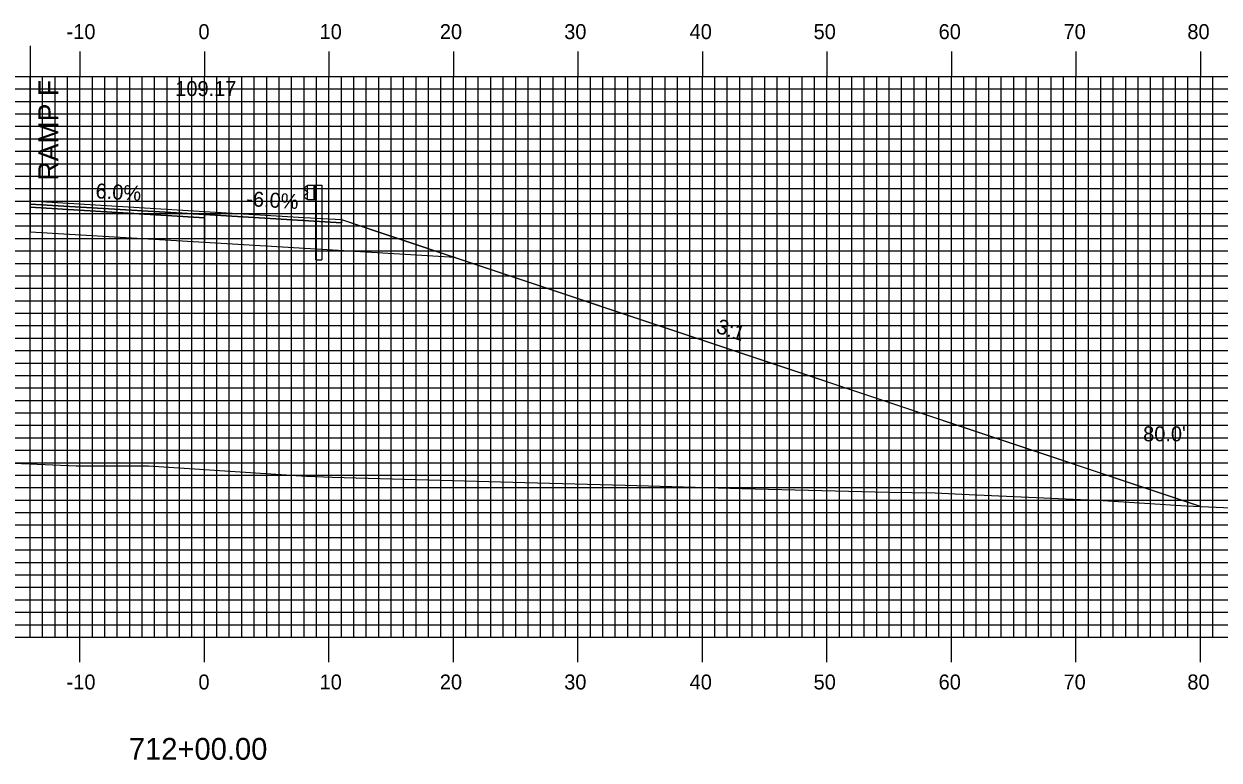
# Model space of a CAD drawing. Extents: x 855297 to 855640, y 364366 to 364586.
# Drawn here: x 855448.3 to 855544.3, y 364433.9 to 364493 of the extents above; entities that cross this region are included whole.
import ezdxf

# ---------------------------------------------------------------- set-up
doc = ezdxf.new("R2010")
doc.units = 0
for name, color, linetype in [('ANNOTATION', 7, 'Continuous'), ('D_Drainage_Culvert', 7, 'Continuous'), ('D_Guardrail_Beam_Rt', 7, 'Continuous'), ('D_Roadway_Centerline', 7, 'Continuous'), ('D_Roadway_Centerline_Text', 7, 'Continuous'), ('D_Roadway_Edge_Shoulder', 7, 'Continuous'), ('D_Roadway_Edge_TW', 7, 'Continuous'), ('D_Roadway_Pavement', 7, 'Continuous'), ('D_Roadway_SlopeLines', 7, 'Continuous'), ('D_Roadway_SubGrade', 7, 'Continuous'), ('D_Text_Standard', 7, 'Continuous'), ('H_V ANNOTATION', 7, 'Continuous'), ('MAJOR', 7, 'Continuous'), ('MINOR', 7, 'Continuous'), ('S_Roadway_Centerline', 7, 'Continuous')]:
    doc.layers.add(name, color=color, linetype=linetype)

msp = doc.modelspace()

# ---------------------------------------------------------------- linework, layer by layer
at = {"layer": 'D_Drainage_Culvert'}
msp.add_lwpolyline([(855473.77, 364477.294), (855476.77, 364476.294), (855542.672, 364454.326)], dxfattribs=at)
at = {"layer": 'D_Guardrail_Beam_Rt'}
for p, q in [((855470.951, 364479.953), (855470.807, 364479.853)), ((855470.807, 364479.71), (855471.003, 364479.573)), ((855471.003, 364479.374), (855470.807, 364479.238)), ((855471.041, 364479.974), (855470.967, 364479.959)), ((855471.036, 364479.509), (855471.036, 364479.439)), ((855471.041, 364480.057), (855471.728, 364480.057)), ((855471.041, 364478.891), (855471.041, 364480.057)), ((855471.562, 364480.057), (855471.562, 364478.891)), ((855471.666, 364480.057), (855471.666, 364478.891)), ((855471.728, 364480.057), (855472.199, 364480.057)), ((855471.728, 364480.057), (855471.728, 364478.891)), ((855472.199, 364480.057), (855472.199, 364474.057)), ((855470.807, 364479.095), (855470.951, 364478.995)), ((855470.967, 364478.989), (855471.041, 364478.974)), ((855471.728, 364478.891), (855471.041, 364478.891)), ((855471.707, 364474.057), (855471.707, 364478.891)), ((855471.707, 364474.057), (855472.199, 364474.057))]:
    msp.add_line(p, q, dxfattribs=at)
for centre, major_axis, start_param, end_param in [((855470.858, 364479.781), (-0.0877, 0), 5.323254, 7.243116), ((855470.975, 364479.919), (-0.0417, 0), 4.907132, 5.323254), ((855470.957, 364479.509), (0.0789, 0), 0, 0.959931), ((855470.957, 364479.439), (0.0789, 0), 5.323254, 6.283185), ((855470.858, 364479.167), (-0.0877, 0), 5.323254, 7.243116), ((855470.975, 364479.029), (-0.0417, 0), 0.959931, 1.376053)]:
    msp.add_ellipse(centre, major_axis=major_axis, ratio=0.995501, start_param=start_param, end_param=end_param, dxfattribs=at)
at = {"layer": 'D_Roadway_Centerline'}
msp.add_lwpolyline([(855448.77, 364478.794), (855462.77, 364477.954), (855470.77, 364477.474), (855473.77, 364477.294), (855482.916, 364474.245), (855542.672, 364454.326)], dxfattribs=at)
at = {"layer": 'D_Roadway_Edge_Shoulder'}
msp.add_lwpolyline([(855462.77, 364477.954), (855470.77, 364477.474), (855470.77, 364477.474), (855473.77, 364477.294), (855473.77, 364477.044), (855462.77, 364477.704)], close=True, dxfattribs=at)
at = {"layer": 'D_Roadway_Edge_TW'}
msp.add_lwpolyline([(855448.77, 364478.794), (855462.77, 364477.954), (855462.77, 364477.704), (855448.77, 364478.544)], close=True, dxfattribs=at)
at = {"layer": 'D_Roadway_Pavement'}
msp.add_lwpolyline([(855448.77, 364478.544), (855462.77, 364477.704), (855462.77, 364477.454), (855448.77, 364478.294)], close=True, dxfattribs=at)
msp.add_lwpolyline([(855462.77, 364477.704), (855462.77, 364477.454)], dxfattribs=at)
msp.add_lwpolyline([(855462.77, 364477.704), (855462.77, 364477.454)], dxfattribs=at)
at = {"layer": 'D_Roadway_SlopeLines'}
msp.add_line((855473.77, 364477.294), (855542.801, 364454.284), dxfattribs=at)
at = {"layer": 'D_Roadway_SubGrade'}
msp.add_line((855448.77, 364491.251), (855448.77, 364476.294), dxfattribs=at)
for points in [[(855448.77, 364478.294), (855462.77, 364477.454), (855462.77, 364475.454), (855448.77, 364476.294)], [(855462.77, 364477.454), (855462.77, 364477.704), (855473.77, 364477.044), (855473.77, 364477.294), (855482.916, 364474.245), (855462.77, 364475.454)]]:
    msp.add_lwpolyline(points, close=True, dxfattribs=at)
at = {"layer": 'MAJOR'}
for p, q in [((855452.77, 364490.791), (855452.77, 364488.787)), ((855462.77, 364490.791), (855462.77, 364488.787)), ((855472.77, 364490.791), (855472.77, 364488.787)), ((855482.77, 364490.791), (855482.77, 364488.787)), ((855492.77, 364490.791), (855492.77, 364488.787)), ((855502.77, 364490.791), (855502.77, 364488.787)), ((855512.77, 364490.791), (855512.77, 364488.787)), ((855522.77, 364490.791), (855522.77, 364488.787)), ((855532.77, 364490.791), (855532.77, 364488.787)), ((855542.77, 364490.791), (855542.77, 364488.787)), ((855322.77, 364488.787), (855602.77, 364488.787)), ((855322.77, 364488.787), (855602.77, 364488.787)), ((855452.77, 364443.787), (855452.77, 364488.787)), ((855462.77, 364443.787), (855462.77, 364488.787)), ((855472.77, 364443.787), (855472.77, 364488.787)), ((855482.77, 364443.787), (855482.77, 364488.787)), ((855492.77, 364443.787), (855492.77, 364488.787)), ((855502.77, 364443.787), (855502.77, 364488.787)), ((855512.77, 364443.787), (855512.77, 364488.787)), ((855522.77, 364443.787), (855522.77, 364488.787)), ((855532.77, 364443.787), (855532.77, 364488.787)), ((855542.77, 364443.787), (855542.77, 364488.787)), ((855322.77, 364483.787), (855602.77, 364483.787)), ((855322.77, 364478.787), (855602.77, 364478.787)), ((855322.77, 364473.787), (855602.77, 364473.787)), ((855322.77, 364468.787), (855602.77, 364468.787)), ((855322.77, 364463.787), (855602.77, 364463.787)), ((855322.77, 364458.787), (855602.77, 364458.787)), ((855322.77, 364453.787), (855602.77, 364453.787)), ((855322.77, 364448.787), (855602.77, 364448.787)), ((855322.77, 364443.787), (855602.77, 364443.787)), ((855322.77, 364443.787), (855602.77, 364443.787)), ((855452.77, 364441.783), (855452.77, 364443.787)), ((855462.77, 364441.783), (855462.77, 364443.787)), ((855472.77, 364441.783), (855472.77, 364443.787)), ((855482.77, 364441.783), (855482.77, 364443.787)), ((855492.77, 364441.783), (855492.77, 364443.787)), ((855502.77, 364441.783), (855502.77, 364443.787)), ((855512.77, 364441.783), (855512.77, 364443.787)), ((855522.77, 364441.783), (855522.77, 364443.787)), ((855532.77, 364441.783), (855532.77, 364443.787)), ((855542.77, 364441.783), (855542.77, 364443.787))]:
    msp.add_line(p, q, dxfattribs=at)
at = {"layer": 'MINOR'}
for p, q in [((855448.77, 364443.787), (855448.77, 364488.787)), ((855449.77, 364443.787), (855449.77, 364488.787)), ((855450.77, 364443.787), (855450.77, 364488.787)), ((855451.77, 364443.787), (855451.77, 364488.787)), ((855453.77, 364443.787), (855453.77, 364488.787)), ((855454.77, 364443.787), (855454.77, 364488.787)), ((855455.77, 364443.787), (855455.77, 364488.787)), ((855456.77, 364443.787), (855456.77, 364488.787)), ((855457.77, 364443.787), (855457.77, 364488.787)), ((855458.77, 364443.787), (855458.77, 364488.787)), ((855459.77, 364443.787), (855459.77, 364488.787)), ((855460.77, 364443.787), (855460.77, 364488.787)), ((855461.77, 364443.787), (855461.77, 364488.787)), ((855463.77, 364443.787), (855463.77, 364488.787)), ((855464.77, 364443.787), (855464.77, 364488.787)), ((855465.77, 364443.787), (855465.77, 364488.787)), ((855466.77, 364443.787), (855466.77, 364488.787)), ((855467.77, 364443.787), (855467.77, 364488.787)), ((855468.77, 364443.787), (855468.77, 364488.787)), ((855469.77, 364443.787), (855469.77, 364488.787)), ((855470.77, 364443.787), (855470.77, 364488.787)), ((855471.77, 364443.787), (855471.77, 364488.787)), ((855473.77, 364443.787), (855473.77, 364488.787)), ((855474.77, 364443.787), (855474.77, 364488.787)), ((855475.77, 364443.787), (855475.77, 364488.787)), ((855476.77, 364443.787), (855476.77, 364488.787)), ((855477.77, 364443.787), (855477.77, 364488.787)), ((855478.77, 364443.787), (855478.77, 364488.787)), ((855479.77, 364443.787), (855479.77, 364488.787)), ((855480.77, 364443.787), (855480.77, 364488.787)), ((855481.77, 364443.787), (855481.77, 364488.787)), ((855483.77, 364443.787), (855483.77, 364488.787)), ((855484.77, 364443.787), (855484.77, 364488.787)), ((855485.77, 364443.787), (855485.77, 364488.787)), ((855486.77, 364443.787), (855486.77, 364488.787)), ((855487.77, 364443.787), (855487.77, 364488.787)), ((855488.77, 364443.787), (855488.77, 364488.787)), ((855489.77, 364443.787), (855489.77, 364488.787)), ((855490.77, 364443.787), (855490.77, 364488.787)), ((855491.77, 364443.787), (855491.77, 364488.787)), ((855493.77, 364443.787), (855493.77, 364488.787)), ((855494.77, 364443.787), (855494.77, 364488.787)), ((855495.77, 364443.787), (855495.77, 364488.787)), ((855496.77, 364443.787), (855496.77, 364488.787)), ((855497.77, 364443.787), (855497.77, 364488.787)), ((855498.77, 364443.787), (855498.77, 364488.787)), ((855499.77, 364443.787), (855499.77, 364488.787)), ((855500.77, 364443.787), (855500.77, 364488.787)), ((855501.77, 364443.787), (855501.77, 364488.787)), ((855503.77, 364443.787), (855503.77, 364488.787)), ((855504.77, 364443.787), (855504.77, 364488.787)), ((855505.77, 364443.787), (855505.77, 364488.787)), ((855506.77, 364443.787), (855506.77, 364488.787)), ((855507.77, 364443.787), (855507.77, 364488.787)), ((855508.77, 364443.787), (855508.77, 364488.787)), ((855509.77, 364443.787), (855509.77, 364488.787)), ((855510.77, 364443.787), (855510.77, 364488.787)), ((855511.77, 364443.787), (855511.77, 364488.787)), ((855513.77, 364443.787), (855513.77, 364488.787)), ((855514.77, 364443.787), (855514.77, 364488.787)), ((855515.77, 364443.787), (855515.77, 364488.787)), ((855516.77, 364443.787), (855516.77, 364488.787)), ((855517.77, 364443.787), (855517.77, 364488.787)), ((855518.77, 364443.787), (855518.77, 364488.787)), ((855519.77, 364443.787), (855519.77, 364488.787)), ((855520.77, 364443.787), (855520.77, 364488.787)), ((855521.77, 364443.787), (855521.77, 364488.787)), ((855523.77, 364443.787), (855523.77, 364488.787)), ((855524.77, 364443.787), (855524.77, 364488.787)), ((855525.77, 364443.787), (855525.77, 364488.787)), ((855526.77, 364443.787), (855526.77, 364488.787)), ((855527.77, 364443.787), (855527.77, 364488.787)), ((855528.77, 364443.787), (855528.77, 364488.787)), ((855529.77, 364443.787), (855529.77, 364488.787)), ((855530.77, 364443.787), (855530.77, 364488.787)), ((855531.77, 364443.787), (855531.77, 364488.787)), ((855533.77, 364443.787), (855533.77, 364488.787)), ((855534.77, 364443.787), (855534.77, 364488.787)), ((855535.77, 364443.787), (855535.77, 364488.787)), ((855536.77, 364443.787), (855536.77, 364488.787)), ((855537.77, 364443.787), (855537.77, 364488.787)), ((855538.77, 364443.787), (855538.77, 364488.787)), ((855539.77, 364443.787), (855539.77, 364488.787)), ((855540.77, 364443.787), (855540.77, 364488.787)), ((855541.77, 364443.787), (855541.77, 364488.787)), ((855543.77, 364443.787), (855543.77, 364488.787)), ((855322.77, 364487.787), (855602.77, 364487.787)), ((855322.77, 364486.787), (855602.77, 364486.787)), ((855322.77, 364485.787), (855602.77, 364485.787)), ((855322.77, 364484.787), (855602.77, 364484.787)), ((855322.77, 364482.787), (855602.77, 364482.787)), ((855322.77, 364481.787), (855602.77, 364481.787)), ((855322.77, 364480.787), (855602.77, 364480.787)), ((855322.77, 364479.787), (855602.77, 364479.787)), ((855322.77, 364477.787), (855602.77, 364477.787)), ((855322.77, 364476.787), (855602.77, 364476.787)), ((855322.77, 364475.787), (855602.77, 364475.787)), ((855322.77, 364474.787), (855602.77, 364474.787)), ((855322.77, 364472.787), (855602.77, 364472.787)), ((855322.77, 364471.787), (855602.77, 364471.787)), ((855322.77, 364470.787), (855602.77, 364470.787)), ((855322.77, 364469.787), (855602.77, 364469.787)), ((855322.77, 364467.787), (855602.77, 364467.787)), ((855322.77, 364466.787), (855602.77, 364466.787)), ((855322.77, 364465.787), (855602.77, 364465.787)), ((855322.77, 364464.787), (855602.77, 364464.787)), ((855322.77, 364462.787), (855602.77, 364462.787)), ((855322.77, 364461.787), (855602.77, 364461.787)), ((855322.77, 364460.787), (855602.77, 364460.787)), ((855322.77, 364459.787), (855602.77, 364459.787)), ((855322.77, 364457.787), (855602.77, 364457.787)), ((855322.77, 364456.787), (855602.77, 364456.787)), ((855322.77, 364455.787), (855602.77, 364455.787)), ((855322.77, 364454.787), (855602.77, 364454.787)), ((855322.77, 364452.787), (855602.77, 364452.787)), ((855322.77, 364451.787), (855602.77, 364451.787)), ((855322.77, 364450.787), (855602.77, 364450.787)), ((855322.77, 364449.787), (855602.77, 364449.787)), ((855322.77, 364447.787), (855602.77, 364447.787)), ((855322.77, 364446.787), (855602.77, 364446.787)), ((855322.77, 364445.787), (855602.77, 364445.787)), ((855322.77, 364444.787), (855602.77, 364444.787))]:
    msp.add_line(p, q, dxfattribs=at)
at = {"layer": 'S_Roadway_Centerline'}
msp.add_lwpolyline([(855440.564, 364458.035), (855452.478, 364457.546), (855458.282, 364457.535), (855470.98, 364456.71), (855473.027, 364456.621), (855488.518, 364456.21), (855496.568, 364455.978), (855505.948, 364455.713), (855517.718, 364455.431), (855521.467, 364455.37), (855523.612, 364455.268), (855534.943, 364454.753), (855541.62, 364454.337), (855558.442, 364453.582), (855558.556, 364453.578), (855558.609, 364453.576), (855558.761, 364453.571), (855572.127, 364453.192), (855576.708, 364452.909), (855585.53, 364452.635), (855594.059, 364452.132), (855597.716, 364451.969), (855602.77, 364451.956)], dxfattribs=at)

# ---------------------------------------------------------------- texts
at = {"layer": 'ANNOTATION'}
for s, height, rotation, p in [('RAMP F', 1.6, 90, (855451.031, 364480.431)), ('6.0%', 1.2, 356.56637, (855454.003, 364479.015)), ('-6.0%', 1.2, 356.56637, (855466.104, 364478.392)), ('3:1', 1.2, 341.56505, (855503.801, 364468.238))]:
    msp.add_text(s, height=height, rotation=rotation, dxfattribs=at).set_placement(p)
at = {"layer": 'D_Roadway_Centerline_Text'}
msp.add_text('109.17', height=1.2, dxfattribs=at).set_placement((855460.427, 364487.216))
at = {"layer": 'D_Text_Standard'}
msp.add_text("80.0'", height=1.2, dxfattribs=at).set_placement((855538.17, 364459.504))
at = {"layer": 'H_V ANNOTATION'}
for s, height, p in [('-10', 1.2, (855451.7, 364491.787)), ('0', 1.2, (855462.288, 364491.787)), ('10', 1.2, (855472.021, 364491.787)), ('20', 1.2, (855481.678, 364491.787)), ('30', 1.2, (855491.667, 364491.787)), ('40', 1.2, (855501.742, 364491.787)), ('50', 1.2, (855511.699, 364491.787)), ('60', 1.2, (855521.742, 364491.787)), ('70', 1.2, (855531.774, 364491.787)), ('80', 1.2, (855541.721, 364491.787)), ('-10', 1.2, (855451.7, 364439.587)), ('0', 1.2, (855462.288, 364439.587)), ('10', 1.2, (855472.021, 364439.587)), ('20', 1.2, (855481.678, 364439.587)), ('30', 1.2, (855491.667, 364439.587)), ('40', 1.2, (855501.742, 364439.587)), ('50', 1.2, (855511.699, 364439.587)), ('60', 1.2, (855521.742, 364439.587)), ('70', 1.2, (855531.774, 364439.587)), ('80', 1.2, (855541.721, 364439.587)), ('712+00.00', 1.75, (855456.699, 364433.943))]:
    msp.add_text(s, height=height, dxfattribs=at).set_placement(p)

doc.saveas('drawing.dxf')
